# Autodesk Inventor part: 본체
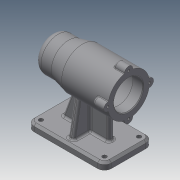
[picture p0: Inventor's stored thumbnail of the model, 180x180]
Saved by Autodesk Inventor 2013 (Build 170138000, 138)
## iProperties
Created: 2019-07
Part Number: 본체
Material: 일반
Document SubType Name: Modeling
Designer: a
Density: 1 g/cm^3
Author: a
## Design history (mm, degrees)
sketch "스케치1"
  geometry: L1 (-56, 0)-(56, 0); L2 (-56, 0)-(-56, 25); L3 (-56, 25)-(-31, 25); L4 (-31, 25)-(-11, 30); L5 (-11, 30)-(56, 30); L6 (56, 30)-(56, 0); L7 (-50, 0)-(-50, 10.5); L8 (-50, 10.5)-(-47, 10.5); L9 (-47, 10.5)-(-47, 16); L10 (-47, 16)-(-43, 16); L11 (-43, 16)-(-43, 17.5); L12 (-43, 17.5)-(-25, 17.5); L13 (-25, 17.5)-(-25, 21); L14 (-25, 21)-(-13, 21); L15 (-13, 21)-(-13, 24); L16 (-13, 24)-(41, 24); L17 (41, 24)-(41, 21); L18 (41, 21)-(56, 21); 2 further points
  constraints: 36 end point, 11 parallel, 5 perpendicular, 2 point on line, 1 coincident, 1 horizontal, 1 midpoint
  dimensions: "d0" = 112 distance of L1.start L1.end; "d1" = 42 diameter of L18 L1; "d2" = 48 diameter of L16 L1; "d3" = 42 diameter of L14 L1; "d4" = 35 diameter of L12 L1; "d5" = 32 diameter of L10 L1; "d6" = 21 diameter of L8 L1; "d7" = 50 diameter of L3 L1; "d8" = 60 diameter of L5 L1; "d9" = 15 distance of L17.end L18.end; "d10" = 54 distance of L15.end L16.end; "d11" = 12 distance of L13.end L14.end; "d12" = 18 distance of L11.end L12.end; "d13" = 4 distance of L9.end L10.end; "d14" = 3 distance of L7.end L8.end; "d15" = 25 distance of L2.end L3.end; "d16" = 20 horizontal distance of L3.end L4.end
revolve "회전1" sketch "스케치1" stored, may be unused: angle "d17" = 90 deg
sketch "스케치2"
  geometry: C1 r 21 at (0, 0) reference; C2 r 6 at (0, 30); C3 r 6 at (30, 0); C4 r 6 at (0, -30); C5 r 6 at (-30, 0); A1 r 30 centre (0, 0) between (0, 30) and (30, 0) reference
  constraints: 4 centre point, 4 point on circle, 2 horizontal alignment, 2 vertical alignment
  dimensions: "d18" = 12 diameter of C2; "d19" = 12 diameter of C3; "d20" = 12 diameter of C4; "d21" = 12 diameter of C5
extrude "돌출1" join sketch "스케치2" distance "d22" = 16; taper "d23" = 0 deg
sketch "스케치3"
  geometry: A1 r 6 centre (-30, -30) between (-35.97, -29.4) and (-24.03, -29.4) reference; A2 r 6 centre (0, 0) between (-0.6, -5.97) and (-0.6, 5.97) reference; A3 r 6 centre (-30, 30) between (-24.03, 29.4) and (-35.97, 29.4) reference; A4 r 6 centre (-60, 0) between (-59.4, 5.97) and (-59.4, -5.97) reference; 4 further points
  constraints: 4 coincident
hole "구멍1" sketch "스케치3" at (-30, 30), (0, 0), (-30, -30), (-60, 0) diameter "d24" = 3.242; stored, may be unused: countersink angle "d28" = 90 deg, drill point angle "d30" = 118 deg; dims "d25" = 8, "d26" = 4, "d27" = 2, "d29" = 11
node "작업 평면1"
sketch "스케치4"
  geometry: L1 (56, 35)-(-56, 35); L2 (-56, 35)-(-56, -35); L3 (-56, -35)-(56, -35); L4 (56, -35)-(56, 35); L5 (56, 35)-(-56, -35); L6 (-56, 35)-(56, -35); 1 further point
  constraints: 12 end point, 2 midpoint, 2 parallel, 1 horizontal, 1 perpendicular
  dimensions: "d32" = 112 distance of L3.end L2.end; "d33" = 70 distance of L2.end L1.end
extrude "돌출2" join sketch "스케치4" distance "d34" = 10; taper "d35" = 0 deg
fillet "모깎기1" dims "d36" = 10
chamfer "모따기1" distance "d37" = 3; stored, may be unused: second distance "d38" = 2, angle "d39" = 45 deg
sketch "스케치5"
  geometry: A1 r 7 centre (46, -25) between (46, -32) and (53, -25) reference; A2 r 7 centre (46, 25) between (53, 25) and (46, 32) reference; A3 r 7 centre (-46, 25) between (-46, 32) and (-53, 25) reference; A4 r 7 centre (-46, -25) between (-53, -25) and (-46, -32) reference; 5 further points
  constraints: 4 coincident
hole "구멍2" sketch "스케치5" at (-46, 25), (46, 25), (46, -25), (-46, -25) diameter "d40" = 6; stored, may be unused: countersink angle "d44" = 90 deg, drill point angle "d46" = 118 deg; dims "d41" = 8, "d42" = 4, "d43" = 2, "d45" = 11
sketch "스케치9"
  geometry: L1 (-70, 25)-(-70, -25) reference; L2 (-70, -22)-(-70, -28) reference; L3 (-70, -25)-(-70, -32) reference; L4 (-70, 32)-(-70, 25) reference; L5 (-80, 35)-(-73, 35) reference; L6 (-73, -35)-(-80, -35) reference; L7 (-22.666, -19.654)-(-70, -28); L8 (-70, 28)-(-22.666, 19.654); L9 (-22.666, 19.654)-(-30, 0); L10 (-22.666, -19.654)-(-30, 0); L11 (-70, 28)-(-70, -28); A1 r 30 centre (0, 0) between (-22.666, -19.654) and (-22.666, 19.654) reference; 1 further point
  constraints: 10 end point, 3 point on circle, 2 point on line, 1 horizontal alignment, 1 perpendicular
  dimensions: "d77" = 100 deg angle of L1 L7; "d79" = 100 deg angle of L1 L8; "d80" = 7 distance from line of L5 L8.start; "d81" = 7 distance from line of L7.end L6
extrude "돌출5" join sketch "스케치9" stored distance "d82" = 8; taper "d83" = 0 deg
sketch "스케치10"
  geometry: L1 (-31, -25)-(-11, -30) reference; L2 (-56, -25)-(-31, -25) reference; L3 (-46, -70)-(46, -70) reference; L4 (-53, -70)-(-46, -70) reference; L5 (46, -70)-(53, -70) reference; L6 (-36, -70)-(-20.57, -27.607); L7 (31, -27.607)-(31, -70); L8 (-4, -22.666)-(-4, -70) reference; L9 (4, -70)-(4, -22.666) reference; L10 (-36, -70)-(-4, -70); L11 (-4, -70)-(-4, -30); L12 (4, -70)-(4, -27.607); L13 (4, -70)-(31, -70); L14 (-56, -80)-(-56, -73) reference; L15 (56, -73)-(56, -80) reference; L16 (-20.57, -27.607)-(-4, -30); L17 (4, -27.607)-(31, -27.607); 1 further point
  constraints: 16 end point, 5 point on line, 3 collinear, 2 perpendicular
  dimensions: "d84" = 110 deg angle of L3 L6; "d85" = 20 distance from line of L14 L6.start; "d86" = 25 distance from line of L15 L7.end; "d98" = 42.39259 distance of L7.start L7.end
extrude "돌출6" join sketch "스케치10" stored distance "d87" = 8; taper "d88" = 0 deg
fillet "모깎기3" dims "d89" = 3
fillet "모깎기4" dims "d90" = 3
fillet "모깎기5" dims "d91" = 0.3
chamfer "모따기2" distance "d92" = 1; stored, may be unused: second distance "d93" = 2, angle "d94" = 45 deg
fillet "모깎기6" dims "d95" = 3
fillet "모깎기7" dims "d96" = 1
fillet "모깎기8" dims "d97" = 10
node "솔리드1"
